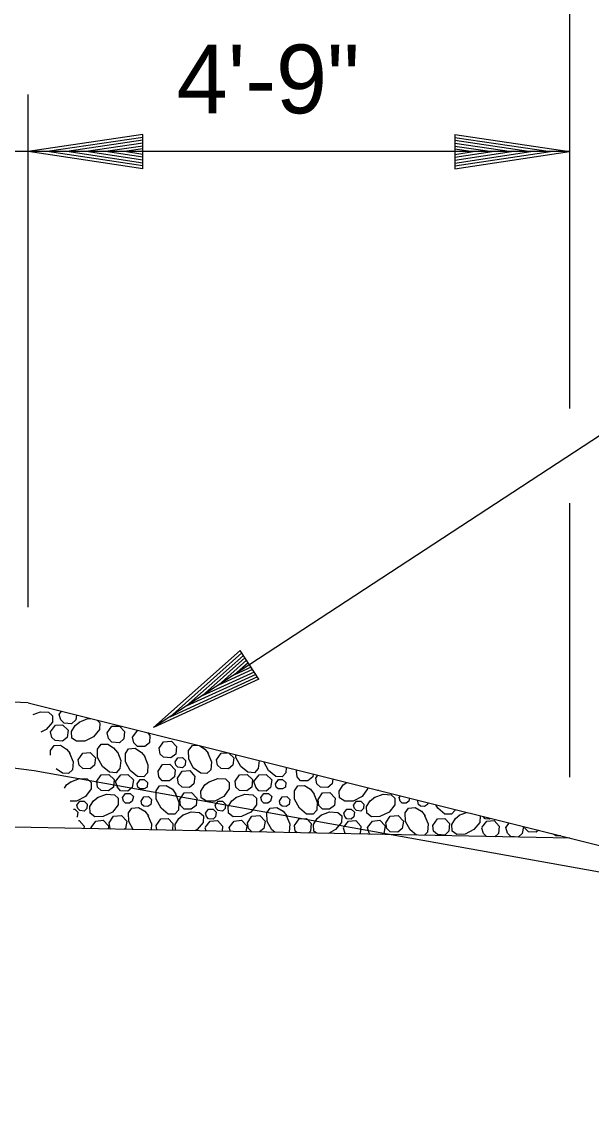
# Model space of a CAD drawing. Extents: x 2478 to 3210, y 439 to 841.
# Drawn here: x 3058.28 to 3068.23, y 589.18 to 608.39 of the extents above; entities that cross this region are included whole.
import ezdxf

# ---------------------------------------------------------------- set-up
doc = ezdxf.new("R2010")
doc.units = 0
for name, color, linetype in [('R_Annotation', 7, 'Continuous'), ('R_Dimension', 7, 'Continuous'), ('R_Exist Surface', 7, 'Continuous')]:
    doc.layers.add(name, color=color, linetype=linetype)

msp = doc.modelspace()

# ---------------------------------------------------------------- linework, layer by layer
at = {"layer": 'R_Annotation'}
for p, q in [((3058.387, 596.498), (3050.387, 596.818)), ((3058.387, 596.498), (3078.387, 591.498)), ((3067.845, 594.133), (3048.387, 594.522))]:
    msp.add_line(p, q, dxfattribs=at)
at = {"layer": 'R_Dimension'}
for p, q in [((3067.845, 601.641), (3067.845, 609.746)), ((3058.387, 598.168), (3058.387, 607.125)), ((3060.387, 606.425), (3058.387, 606.125)), ((3060.387, 605.825), (3060.387, 606.425)), ((3065.839, 606.425), (3067.839, 606.125)), ((3065.839, 606.425), (3065.839, 605.825)), ((3060.387, 606.375), (3058.721, 606.125)), ((3060.387, 606.324), (3059.065, 606.125)), ((3060.387, 606.274), (3059.398, 606.125)), ((3060.387, 606.223), (3059.737, 606.125)), ((3065.839, 606.375), (3067.505, 606.125)), ((3065.839, 606.324), (3067.161, 606.125)), ((3065.839, 606.274), (3066.828, 606.125)), ((3065.839, 606.222), (3066.489, 606.125)), ((3067.845, 606.125), (2988.928, 606.125)), ((3060.387, 605.825), (3058.387, 606.125)), ((3060.387, 605.875), (3058.721, 606.125)), ((3060.387, 605.926), (3059.065, 606.125)), ((3060.387, 605.976), (3059.398, 606.125)), ((3060.387, 606.028), (3059.737, 606.125)), ((3060.387, 606.172), (3060.071, 606.125)), ((3060.387, 606.078), (3060.071, 606.125)), ((3065.839, 606.172), (3066.155, 606.125)), ((3065.839, 605.825), (3067.839, 606.125)), ((3065.839, 606.027), (3066.489, 606.125)), ((3065.839, 605.926), (3067.161, 606.125)), ((3065.839, 605.875), (3067.505, 606.125)), ((3065.839, 605.976), (3066.828, 606.125)), ((3065.839, 606.078), (3066.155, 606.125)), ((3067.845, 595.201), (3067.845, 599.983)), ((3062.09, 597.411), (3060.579, 596.067)), ((3062.117, 597.369), (3060.859, 596.249)), ((3062.418, 596.909), (3062.09, 597.411)), ((3062.145, 597.327), (3061.147, 596.437)), ((3062.172, 597.285), (3061.426, 596.619)), ((3062.2, 597.242), (3061.709, 596.805)), ((3062.228, 597.199), (3061.989, 596.987)), ((3062.363, 596.993), (3061.147, 596.437)), ((3062.335, 597.035), (3061.426, 596.619)), ((3062.307, 597.079), (3061.709, 596.805)), ((3062.279, 597.121), (3061.989, 596.987)), ((3062.418, 596.909), (3060.579, 596.067)), ((3062.39, 596.951), (3060.859, 596.249)), ((3058.93, 596.293), (3058.972, 596.351)), ((3063.07, 595.303), (3063.084, 595.324)), ((3063.41, 595.183), (3063.444, 595.234)), ((3064.865, 594.843), (3064.886, 594.873)), ((3065.19, 594.783), (3065.198, 594.795)), ((3065.915, 594.533), (3066.042, 594.584)), ((3059.491, 594.3), (3059.485, 594.323)), ((3060.632, 594.277), (3060.62, 594.358)), ((3061.493, 594.26), (3061.48, 594.308)), ((3061.918, 594.252), (3061.9, 594.323)), ((3066.73, 594.323), (3066.788, 594.398))]:
    msp.add_line(p, q, dxfattribs=at)
for points in [[(3085.799, 609.401), (3080.944, 609.401), (3060.579, 596.067)], [(3058.474, 596.293), (3058.605, 596.343), (3058.745, 596.333), (3058.81, 596.273), (3058.81, 596.158), (3058.705, 596.033), (3058.607, 595.983)], [(3059.23, 596.287), (3059.22, 596.203), (3059.145, 596.133), (3059.015, 596.143), (3058.96, 596.203), (3058.93, 596.293)], [(3059.28, 596.163), (3059.43, 596.223), (3059.506, 596.218)], [(3058.78, 595.993), (3058.865, 596.108), (3058.99, 596.113), (3059.085, 596.023), (3059.07, 595.893), (3058.985, 595.828), (3058.86, 595.838), (3058.8, 595.893), (3058.78, 595.993)], [(3059.592, 596.197), (3059.64, 596.148), (3059.635, 596.033), (3059.53, 595.903), (3059.38, 595.828), (3059.23, 595.828), (3059.15, 595.883), (3059.145, 595.998), (3059.21, 596.103), (3059.285, 596.163)], [(3059.77, 595.973), (3059.85, 596.088), (3059.98, 596.093), (3060.07, 595.998), (3060.06, 595.868), (3059.98, 595.798), (3059.85, 595.813), (3059.79, 595.873), (3059.77, 595.973)], [(3060.21, 595.898), (3060.3, 596.018), (3060.304, 596.018)], [(3060.469, 595.977), (3060.515, 595.928), (3060.505, 595.798), (3060.425, 595.733), (3060.295, 595.738), (3060.235, 595.798), (3060.21, 595.898)], [(3060.675, 595.708), (3060.75, 595.818), (3060.89, 595.828), (3060.975, 595.733), (3060.965, 595.603), (3060.88, 595.538), (3060.75, 595.548), (3060.69, 595.603), (3060.675, 595.708)], [(3058.778, 595.582), (3058.775, 595.668), (3058.84, 595.753), (3058.95, 595.758), (3059.06, 595.688), (3059.12, 595.613)], [(3059.26, 595.503), (3059.34, 595.618), (3059.47, 595.628), (3059.565, 595.538), (3059.545, 595.408), (3059.47, 595.343), (3059.34, 595.348), (3059.28, 595.408), (3059.26, 595.503)], [(3059.945, 595.643), (3060.005, 595.488), (3059.99, 595.348), (3059.925, 595.278), (3059.81, 595.288), (3059.685, 595.388), (3059.6, 595.543), (3059.6, 595.688), (3059.66, 595.773), (3059.78, 595.778), (3059.88, 595.713), (3059.945, 595.633)], [(3060.42, 595.568), (3060.48, 595.413), (3060.47, 595.273), (3060.41, 595.208), (3060.295, 595.213), (3060.17, 595.313), (3060.085, 595.468), (3060.085, 595.613), (3060.14, 595.693), (3060.255, 595.708), (3060.365, 595.633), (3060.425, 595.558)], [(3061.525, 595.618), (3061.59, 595.468), (3061.575, 595.328), (3061.51, 595.263), (3061.4, 595.268), (3061.27, 595.363), (3061.195, 595.518), (3061.19, 595.668), (3061.255, 595.753), (3061.348, 595.757)], [(3061.378, 595.75), (3061.475, 595.688), (3061.535, 595.613)], [(3061.675, 595.503), (3061.755, 595.618), (3061.87, 595.627)], [(3059.11, 595.618), (3059.175, 595.468), (3059.16, 595.328), (3059.095, 595.263), (3058.985, 595.268), (3058.879, 595.346)], [(3060.955, 595.468), (3061, 595.538), (3061.08, 595.543), (3061.135, 595.488), (3061.13, 595.408), (3061.08, 595.363), (3061, 595.373), (3060.965, 595.408), (3060.955, 595.468)], [(3061.892, 595.621), (3061.98, 595.538), (3061.96, 595.408), (3061.885, 595.343), (3061.755, 595.348), (3061.695, 595.408), (3061.675, 595.503)], [(3062.42, 595.49), (3062.42, 595.488), (3062.405, 595.348), (3062.34, 595.278), (3062.225, 595.288), (3062.1, 595.388), (3062.015, 595.543), (3062.015, 595.591)], [(3062.892, 595.371), (3062.885, 595.273), (3062.825, 595.208), (3062.71, 595.213), (3062.585, 595.313), (3062.5, 595.468), (3062.5, 595.469)], [(3059.585, 595.128), (3059.66, 595.243), (3059.795, 595.248), (3059.89, 595.158), (3059.875, 595.023), (3059.79, 594.958), (3059.66, 594.968), (3059.6, 595.023), (3059.585, 595.128)], [(3059.915, 595.123), (3060.005, 595.238), (3060.13, 595.248), (3060.225, 595.153), (3060.205, 595.018), (3060.13, 594.953), (3060, 594.963), (3059.945, 595.023), (3059.915, 595.123)], [(3060.655, 595.303), (3060.735, 595.423), (3060.86, 595.428), (3060.955, 595.328), (3060.945, 595.203), (3060.855, 595.133), (3060.73, 595.138), (3060.67, 595.203), (3060.655, 595.303)], [(3060.995, 595.183), (3061.075, 595.303), (3061.21, 595.313), (3061.295, 595.213), (3061.28, 595.083), (3061.205, 595.018), (3061.075, 595.023), (3061.015, 595.083), (3060.995, 595.183)], [(3062, 595.128), (3062.075, 595.243), (3062.21, 595.248), (3062.305, 595.158), (3062.29, 595.023), (3062.205, 594.958), (3062.075, 594.968), (3062.015, 595.023), (3062, 595.128)], [(3062.33, 595.123), (3062.42, 595.238), (3062.545, 595.248), (3062.64, 595.153), (3062.62, 595.018), (3062.545, 594.953), (3062.415, 594.963), (3062.36, 595.023), (3062.33, 595.123)], [(3063.364, 595.253), (3063.36, 595.203), (3063.27, 595.133), (3063.145, 595.138), (3063.085, 595.203), (3063.07, 595.303)], [(3059.024, 595.007), (3059.06, 595.063), (3059.14, 595.123)], [(3059.135, 595.118), (3059.285, 595.178), (3059.42, 595.168), (3059.485, 595.108), (3059.485, 594.993), (3059.39, 594.863), (3059.23, 594.783), (3059.12, 594.783)], [(3060.29, 595.083), (3060.345, 595.158), (3060.415, 595.158), (3060.47, 595.108), (3060.465, 595.023), (3060.415, 594.993), (3060.335, 594.998), (3060.3, 595.023), (3060.29, 595.083)], [(3060.96, 594.908), (3061.02, 594.763), (3061.01, 594.623), (3060.95, 594.553), (3060.835, 594.553), (3060.71, 594.658), (3060.625, 594.813), (3060.625, 594.958), (3060.68, 595.048), (3060.8, 595.053), (3060.905, 594.988), (3060.965, 594.903)], [(3061.55, 595.118), (3061.7, 595.178), (3061.835, 595.168), (3061.9, 595.108), (3061.9, 594.993), (3061.805, 594.863), (3061.645, 594.783), (3061.5, 594.783), (3061.41, 594.838), (3061.405, 594.953), (3061.475, 595.063), (3061.555, 595.123)], [(3062.705, 595.083), (3062.76, 595.158), (3062.83, 595.158), (3062.885, 595.108), (3062.88, 595.023), (3062.83, 594.993), (3062.75, 594.998), (3062.715, 595.023), (3062.705, 595.083)], [(3063.375, 594.908), (3063.435, 594.763), (3063.425, 594.623), (3063.365, 594.553), (3063.25, 594.553), (3063.125, 594.658), (3063.04, 594.813), (3063.04, 594.958), (3063.095, 595.048), (3063.215, 595.053), (3063.32, 594.988), (3063.38, 594.903)], [(3063.705, 595.168), (3063.695, 595.083), (3063.62, 595.018), (3063.49, 595.023), (3063.43, 595.083), (3063.41, 595.183)], [(3064.315, 595.016), (3064.315, 594.993), (3064.22, 594.863), (3064.06, 594.783), (3063.915, 594.783), (3063.825, 594.838), (3063.82, 594.953), (3063.89, 595.063), (3063.949, 595.107)], [(3059.6, 594.843), (3059.755, 594.903), (3059.895, 594.893), (3059.96, 594.833), (3059.96, 594.718), (3059.86, 594.588), (3059.7, 594.513), (3059.55, 594.508), (3059.47, 594.568), (3059.465, 594.688), (3059.53, 594.788), (3059.61, 594.848)], [(3060.035, 594.843), (3060.085, 594.913), (3060.17, 594.913), (3060.225, 594.863), (3060.205, 594.783), (3060.16, 594.743), (3060.085, 594.748), (3060.055, 594.783), (3060.035, 594.843)], [(3060.36, 594.783), (3060.41, 594.858), (3060.49, 594.863), (3060.54, 594.808), (3060.53, 594.723), (3060.48, 594.688), (3060.41, 594.693), (3060.37, 594.723), (3060.36, 594.783)], [(3061.035, 594.808), (3061.11, 594.923), (3061.24, 594.933), (3061.335, 594.833), (3061.32, 594.703), (3061.235, 594.638), (3061.11, 594.643), (3061.05, 594.703), (3061.035, 594.808)], [(3062.015, 594.843), (3062.17, 594.903), (3062.31, 594.893), (3062.375, 594.833), (3062.375, 594.718), (3062.275, 594.588), (3062.115, 594.513), (3061.965, 594.508), (3061.885, 594.568), (3061.88, 594.688), (3061.945, 594.788), (3062.025, 594.848)], [(3062.45, 594.843), (3062.5, 594.913), (3062.585, 594.913), (3062.64, 594.863), (3062.62, 594.783), (3062.575, 594.743), (3062.5, 594.748), (3062.47, 594.783), (3062.45, 594.843)], [(3062.775, 594.783), (3062.825, 594.858), (3062.905, 594.863), (3062.955, 594.808), (3062.945, 594.723), (3062.895, 594.688), (3062.825, 594.693), (3062.785, 594.723), (3062.775, 594.783)], [(3063.45, 594.808), (3063.525, 594.923), (3063.655, 594.933), (3063.75, 594.833), (3063.735, 594.703), (3063.65, 594.638), (3063.525, 594.643), (3063.465, 594.703), (3063.45, 594.808)], [(3064.43, 594.843), (3064.585, 594.903), (3064.725, 594.893), (3064.79, 594.833), (3064.79, 594.718), (3064.69, 594.588), (3064.53, 594.513), (3064.38, 594.508), (3064.3, 594.568), (3064.295, 594.688), (3064.36, 594.788), (3064.44, 594.848)], [(3064.512, 594.967), (3064.49, 594.968), (3064.484, 594.973)], [(3059.24, 594.713), (3059.29, 594.778), (3059.365, 594.783), (3059.42, 594.728), (3059.415, 594.653), (3059.365, 594.608), (3059.29, 594.618), (3059.255, 594.653), (3059.24, 594.713)], [(3060.221, 594.286), (3060.145, 594.423), (3060.14, 594.578), (3060.2, 594.658), (3060.315, 594.668), (3060.425, 594.603), (3060.49, 594.523)], [(3061.655, 594.713), (3061.705, 594.778), (3061.78, 594.783), (3061.835, 594.728), (3061.83, 594.653), (3061.78, 594.608), (3061.705, 594.618), (3061.67, 594.653), (3061.655, 594.713)], [(3062.692, 594.236), (3062.64, 594.278), (3062.56, 594.423), (3062.555, 594.578), (3062.615, 594.658), (3062.73, 594.668), (3062.84, 594.603), (3062.905, 594.523)], [(3064.07, 594.713), (3064.12, 594.778), (3064.195, 594.783), (3064.25, 594.728), (3064.245, 594.653), (3064.195, 594.608), (3064.12, 594.618), (3064.085, 594.653), (3064.07, 594.713)], [(3065.047, 594.833), (3065.035, 594.783), (3064.99, 594.743), (3064.915, 594.748), (3064.885, 594.783), (3064.865, 594.843)], [(3065.168, 594.187), (3065.055, 594.278), (3064.975, 594.423), (3064.97, 594.578), (3065.03, 594.658), (3065.145, 594.668), (3065.255, 594.603), (3065.32, 594.523)], [(3065.364, 594.754), (3065.36, 594.723), (3065.31, 594.688), (3065.24, 594.693), (3065.2, 594.723), (3065.19, 594.783)], [(3065.841, 594.634), (3065.84, 594.623), (3065.78, 594.553), (3065.665, 594.553), (3065.54, 594.658), (3065.507, 594.718)], [(3059.18, 594.642), (3059.2, 594.643), (3059.255, 594.588), (3059.245, 594.508), (3059.239, 594.503)], [(3059.805, 594.403), (3059.88, 594.518), (3060.015, 594.528), (3060.11, 594.433), (3060.09, 594.303), (3060.072, 594.289)], [(3060.48, 594.528), (3060.54, 594.383), (3060.533, 594.279)], [(3060.62, 594.358), (3060.705, 594.473), (3060.835, 594.478), (3060.915, 594.388), (3060.906, 594.272)], [(3060.96, 594.271), (3060.955, 594.373), (3061.02, 594.478), (3061.095, 594.543)], [(3061.085, 594.533), (3061.235, 594.593), (3061.38, 594.583), (3061.45, 594.523), (3061.445, 594.408), (3061.34, 594.283), (3061.304, 594.264)], [(3061.485, 594.573), (3061.535, 594.638), (3061.615, 594.643), (3061.67, 594.588), (3061.66, 594.508), (3061.615, 594.468), (3061.535, 594.473), (3061.5, 594.513), (3061.485, 594.573)], [(3062.22, 594.403), (3062.295, 594.518), (3062.43, 594.528), (3062.525, 594.433), (3062.505, 594.303), (3062.429, 594.242)], [(3062.895, 594.528), (3062.955, 594.383), (3062.945, 594.238), (3062.939, 594.231)], [(3063.035, 594.358), (3063.12, 594.473), (3063.25, 594.478), (3063.33, 594.388), (3063.32, 594.258), (3063.284, 594.224)], [(3063.424, 594.222), (3063.375, 594.258), (3063.37, 594.373), (3063.435, 594.478), (3063.51, 594.543)], [(3063.5, 594.533), (3063.65, 594.593), (3063.795, 594.583), (3063.865, 594.523), (3063.86, 594.408), (3063.755, 594.283), (3063.632, 594.217)], [(3063.9, 594.573), (3063.95, 594.638), (3064.03, 594.643), (3064.085, 594.588), (3064.075, 594.508), (3064.03, 594.468), (3063.95, 594.473), (3063.915, 594.513), (3063.9, 594.573)], [(3064.635, 594.403), (3064.71, 594.518), (3064.845, 594.528), (3064.94, 594.433), (3064.92, 594.303), (3064.84, 594.238), (3064.71, 594.243), (3064.65, 594.303), (3064.635, 594.403)], [(3065.31, 594.528), (3065.37, 594.383), (3065.36, 594.238), (3065.31, 594.184)], [(3065.45, 594.358), (3065.535, 594.473), (3065.665, 594.478), (3065.745, 594.388), (3065.735, 594.258), (3065.66, 594.188), (3065.535, 594.198), (3065.465, 594.258), (3065.45, 594.358)], [(3066.278, 594.525), (3066.28, 594.523), (3066.275, 594.408), (3066.17, 594.283), (3066.02, 594.203), (3065.87, 594.198), (3065.79, 594.258), (3065.785, 594.373), (3065.85, 594.478), (3065.925, 594.543)], [(3066.458, 594.48), (3066.445, 594.468), (3066.365, 594.473), (3066.331, 594.512)], [(3059.265, 594.442), (3059.28, 594.443), (3059.365, 594.343), (3059.362, 594.303)], [(3059.485, 594.323), (3059.57, 594.433), (3059.7, 594.448), (3059.79, 594.348), (3059.782, 594.294)], [(3059.83, 594.294), (3059.82, 594.303), (3059.805, 594.403)], [(3061.48, 594.323), (3061.565, 594.433), (3061.695, 594.443), (3061.78, 594.343), (3061.773, 594.255)], [(3061.9, 594.323), (3061.985, 594.433), (3062.115, 594.448), (3062.205, 594.348), (3062.189, 594.246)], [(3062.294, 594.244), (3062.235, 594.303), (3062.22, 594.403)], [(3063.085, 594.228), (3063.05, 594.258), (3063.035, 594.358)], [(3063.895, 594.323), (3063.98, 594.433), (3064.11, 594.443), (3064.195, 594.343), (3064.185, 594.218), (3064.173, 594.207)], [(3063.926, 594.212), (3063.92, 594.218), (3063.895, 594.308)], [(3064.315, 594.323), (3064.4, 594.433), (3064.53, 594.448), (3064.62, 594.348), (3064.6, 594.218), (3064.577, 594.199)], [(3064.36, 594.203), (3064.34, 594.223), (3064.315, 594.323)], [(3066.31, 594.323), (3066.395, 594.433), (3066.525, 594.443), (3066.61, 594.343), (3066.6, 594.218), (3066.537, 594.159)], [(3066.387, 594.162), (3066.335, 594.218), (3066.31, 594.308)], [(3067.033, 594.336), (3067.015, 594.218), (3066.94, 594.153), (3066.815, 594.163), (3066.755, 594.223), (3066.73, 594.323)], [(3067.295, 594.271), (3067.255, 594.238), (3067.125, 594.243), (3067.065, 594.303), (3067.061, 594.329)], [(3067.685, 594.173), (3067.6, 594.173), (3067.562, 594.204)]]:
    msp.add_lwpolyline(points, dxfattribs=at)
at = {"layer": 'R_Exist Surface'}
msp.add_lwpolyline([(2971.547, 589.176), (2984.936, 589.495), (2995.981, 592.895), (3003.214, 595.328), (3006.454, 596.336), (3028.393, 596.924), (3047.796, 596.444), (3050.597, 596.328), (3058.493, 595.314), (3072.681, 592.772), (3086.171, 594.044)], dxfattribs=at)

# ---------------------------------------------------------------- texts
at = {"layer": 'R_Annotation'}
msp.add_text('4\'-9"', height=1.2, dxfattribs=at).set_placement((3060.981, 606.795))

doc.saveas('drawing.dxf')
